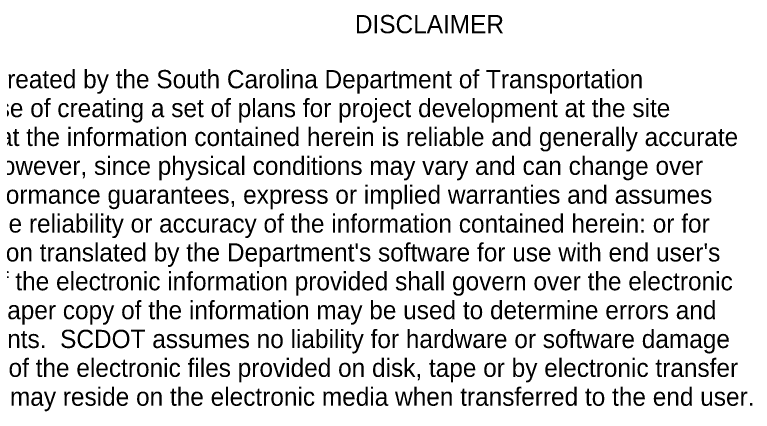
# Model space of a CAD drawing. Extents: x 0 to 4.05, y -2.5 to 2.32.
# Drawn here: x 1.028 to 1.727, y 1.943 to 2.32 of the extents above; entities that cross this region are included whole.
import ezdxf

# ---------------------------------------------------------------- set-up
doc = ezdxf.new("R2010")
doc.units = 0
doc.layers.add('BR_USER NOTES', color=7, linetype='Continuous')

msp = doc.modelspace()

# ---------------------------------------------------------------- texts
at = {"layer": 'BR_USER NOTES'}
for s, height, p in [('DISCLAIMER', 0.017305, (1.35036, 2.30219)), ('These electronic files were created by the South Carolina Department of Transportation', 0.0173049, (0.72861, 2.24994)), ('(SCDOT) for the sole purpose of creating a set of plans for project development at the site', 0.0173049, (0.72861, 2.22254)), ('shown.  SCDOT believes that the information contained herein is reliable and generally accurate', 0.0173049, (0.72861, 2.19513)), ('for the purpose intended.  However, since physical conditions may vary and can change over', 0.0173049, (0.72861, 2.16773)), ('time, SCDOT makes no performance guarantees, express or implied warranties and assumes', 0.0173049, (0.72861, 2.14033)), ('no obligation or liability for the reliability or accuracy of the information contained herein: or for', 0.01730492, (0.72861, 2.11293)), ("the accuracy of the information translated by the Department's software for use with end user's", 0.0173049, (0.72861, 2.08553)), ('software.  The paper copy of the electronic information provided shall govern over the electronic', 0.0173049, (0.72861, 2.05812)), ('files stored copy.  Only the paper copy of the information may be used to determine errors and', 0.0173049, (0.72861, 2.03072)), ('omissions in the bid documents.  SCDOT assumes no liability for hardware or software damage', 0.0173049, (0.72861, 2.00332)), ('that may result from the use of the electronic files provided on disk, tape or by electronic transfer', 0.01730492, (0.72861, 1.97592)), ('due to unknown viruses that may reside on the electronic media when transferred to the end user.', 0.0173049, (0.72861, 1.94851))]:
    msp.add_text(s, height=height, rotation=360, dxfattribs=at).set_placement(p)

doc.saveas('drawing.dxf')
